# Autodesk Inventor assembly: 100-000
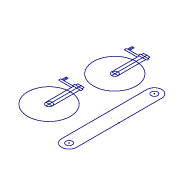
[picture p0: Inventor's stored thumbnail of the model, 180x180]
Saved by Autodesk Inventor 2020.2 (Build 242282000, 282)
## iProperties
Created: 2015-05
Part Number: 100-000
Document SubType Name: Assembly
Designer: F.Stasiak
Manager: www.cadconsulting.pl
Company: Fabian Stasiak CAD Consulting
Author: F.Stasiak
Subject: Zbiór ćwiczeń. Autodesk Inventor 2020. Kurs podstawowy
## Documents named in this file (3)
- C:\2020_Kurs_podstawowy\R6 Zespoły\Warsztat\000-000.iam
- C:\2020_Kurs_podstawowy\R6 Zespoły\Warsztat\Komponenty\000-001.ipt
- C:\2020_Kurs_podstawowy\R6 Zespoły\Warsztat\Komponenty\000-002.ipt
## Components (3 placed, 2 different names)
1. 000-001:1 — Zestawiający:1
2. 000-002:1
3. 000-002:2
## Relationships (1: Mate 1)
- Zestawiający:1 [Mate]: 000-001:1
